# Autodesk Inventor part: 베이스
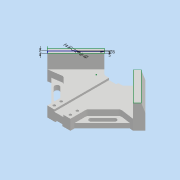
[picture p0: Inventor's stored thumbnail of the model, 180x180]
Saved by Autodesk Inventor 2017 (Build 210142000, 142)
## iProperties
Part Number: 베이스
Material: 일반
Document SubType Name: Modeling
Designer: mrc
Density: 1 g/cm^3
Appearance: 기본값
Author: mrc
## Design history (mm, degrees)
node "스케치1"
sketch "스케치2"
  geometry: L1 (0, 0)-(0, 3.931); L2 (20, -64.853)-(84.853, 0); L3 (84.853, 0)-(0, 84.853); L4 (0, 84.853)-(-84.853, 0); L5 (-84.853, 0)-(-20, -64.853); L6 (84.853, 0)-(-84.853, 0); L7 (0, -64.853)-(-20, -64.853); L8 (0, -64.853)-(20, -64.853); L9 (0, 84.853)-(35.355, 49.497); L10 (0, 84.853)-(-35.355, 49.497); L11 (24.749, 38.891)-(74.246, -10.607); L12 (-35.355, 49.497)-(-16.005, 30.147); L13 (35.355, 49.497)-(16.005, 30.147); L14 (-24.749, 38.891)-(-74.246, -10.607); L15 (0, -64.853)-(0, 30.147); L16 (0, 30.147)-(-16.005, 30.147); L17 (0, 30.147)-(16.005, 30.147); L18 (-20, -36.569)-(-49.497, -7.071); L19 (-84.853, 0)-(-63.64, -21.213); L20 (-74.246, -10.607)-(-49.497, -7.071); L21 (84.853, 0)-(63.64, -21.213); L22 (74.246, -10.607)-(49.497, -7.071); L23 (49.497, -7.071)-(20, -36.569); L24 (-20, -64.853)-(-20, -36.569); L25 (20, -64.853)-(20, -36.569); 4 further points
  constraints: 50 end point, 11 point on line, 3 perpendicular, 3 vertical, 2 horizontal, 2 midpoint, 2 parallel
  dimensions: "d10" = 120 distance of L3.end L2.end; "d13" = 20 distance of L7.start L5.end; "d14" = 20 distance of L7.start L2.start; "d15" = 50 distance of L3.end L9.end; "d16" = 50 distance of L3.end L10.end; "d17" = 15 distance between parallel lines of L3 L11; "d19" = 15 distance between parallel lines of L14 L4; "d21" = 20 distance between parallel lines of L5 L18; "d22" = 30 distance of L4.end L19.end; "d24" = 30 distance of L2.end L21.end; "d101" = 95 distance of L7.start L15.end
extrude "돌출1" new body sketch "스케치2" distance "d25" = 18; taper "d26" = 0 deg
sketch "스케치4"
  geometry: L1 (84.853, 0)-(-84.853, 0); L2 (-49.497, -7.071)-(-74.246, -10.607) reference; L3 (-24.749, 38.891)-(-16.005, 30.147) reference; L4 (-74.246, -10.607)-(-24.749, 38.891); L5 (-24.749, 38.891)-(-35.355, 49.497); L6 (24.749, 38.891)-(74.246, -10.607) reference; L7 (24.749, 38.891)-(35.355, 49.497); L8 (24.749, 38.891)-(74.246, -10.607); L9 (-35.355, 49.497)-(-84.853, 0); L10 (-84.853, 0)-(-74.246, -10.607); L11 (35.355, 49.497)-(84.853, 0); L12 (84.853, 0)-(74.246, -10.607); 2 further points
  constraints: 18 end point, 3 perpendicular, 2 midpoint
  dimensions: "d31" = 70 distance of L7.end L1.start
extrude "돌출2" join sketch "스케치4" distance "d32" = 42; taper "d33" = 0 deg
sketch "스케치5"
  geometry: L1 (0, -84.853)-(84.853, 0); L2 (84.853, 0)-(77.782, 0); L3 (-81.317, 3.536)-(-84.853, 0); L4 (84.853, 0)-(81.317, 3.536); L5 (-49.497, -7.071)-(-74.246, -10.607) reference; L6 (-68.059, -9.723)-(-49.497, -7.071); L7 (20, -36.569)-(20, -64.853) reference; L8 (20, -64.853)-(-20, -64.853) reference; L9 (-20, -64.853)-(-20, -36.569) reference; L10 (-20, -36.569)-(-49.497, -7.071) reference; L11 (-49.497, -7.071)-(-74.246, -10.607) reference; L12 (-74.246, -10.607)-(-84.853, 0) reference; L13 (-84.853, 0)-(-35.355, 49.497) reference; L14 (-35.355, 49.497)-(-16.005, 30.147) reference; L15 (-16.005, 30.147)-(16.005, 30.147) reference; L16 (16.005, 30.147)-(35.355, 49.497) reference; L17 (35.355, 49.497)-(84.853, 0) reference; L18 (84.853, 0)-(74.246, -10.607) reference; L19 (74.246, -10.607)-(49.497, -7.071) reference; L20 (49.497, -7.071)-(20, -36.569) reference; L21 (-20, -36.569)-(-49.497, -7.071) reference; L22 (-49.497, -7.071)-(-20, -36.569); L23 (-20, -64.853)-(-20, -36.569) reference; L24 (-20, -36.569)-(-20, -59.093); L25 (20, -36.569)-(20, -64.853) reference; L26 (20, -58.469)-(20, -36.569); L27 (74.246, -10.607)-(49.497, -7.071) reference; L28 (20, -36.569)-(49.497, -7.071); L29 (49.497, -7.071)-(74.246, -10.607); L30 (-84.853, 0)-(-74.246, -10.607); L31 (-20, -64.853)-(0, -84.853); L32 (0, -77.782)-(-12.929, -64.853); L33 (-20, -57.782)-(-68.059, -9.723); L34 (68.059, -9.723)-(20, -57.782); L35 (12.929, -64.853)-(0, -77.782); 2 further points
  constraints: 34 end point, 11 point on line, 4 collinear, 3 parallel, 1 perpendicular, 1 vertical alignment
extrude "돌출3" join sketch "스케치5" distance "d37" = 8; taper "d38" = 0 deg
sketch "스케치6"
  geometry: L1 (16.005, 30.147)-(-16.005, 30.147) reference; L2 (0, 30.147)-(0, -64.853); L3 (-20, -64.853)-(20, -64.853) reference; L4 (-8, 30.147)-(-8, -66.066); L5 (8, 30.147)-(8, -66.066); L6 (8, 30.147)-(-8, 30.147); L7 (-8, -66.066)-(8, -66.066); 1 further point
  constraints: 10 end point, 2 midpoint, 2 parallel, 1 collinear, 1 horizontal
  dimensions: "d39" = 8 distance between parallel lines of L2 L4; "d40" = 8 distance between parallel lines of L2 L5
extrude "돌출4" cut sketch "스케치6" distance "d41" = 3.5; taper "d42" = 0 deg
sketch "스케치7"
  geometry: L1 (20, -64.853)-(-20, -64.853) reference; L2 (0, -64.853)-(0, 30.147); L3 (-16.005, 30.147)-(16.005, 30.147) reference; L4 (6, -66.066)-(6, 30.147); L5 (-6, -66.066)-(-6, 30.147); L6 (-6, 30.147)-(6, 30.147); L7 (6, -66.066)-(-6, -66.066); 1 further point
  constraints: 10 end point, 3 parallel, 2 midpoint, 1 collinear
  dimensions: "d43" = 6 distance between parallel lines of L2 L4; "d44" = 6 distance between parallel lines of L2 L5
extrude "돌출5" cut sketch "스케치7" distance "d45" = 3; taper "d46" = 0 deg
sketch "스케치8"
  geometry: L1 (-20, -36.569)-(-20, -64.853) reference; L2 (-20, -64.853)-(-6, -64.853) reference; L3 (20, -64.853)-(20, -36.569) reference; L4 (8, -64.853)-(20, -64.853) reference; C1 r 2.25 at (14, -46.853); C2 r 2.25 at (14, -58.853); C3 r 2.25 at (-14, -46.853); C4 r 2.25 at (-14, -58.853); 1 further point
  constraints: 4 centre point
  dimensions: "d47" = 4.5 diameter of C1; "d48" = 4.5 diameter of C2; "d49" = 4.5 diameter of C3; "d50" = 4.5 diameter of C4; "d51" = 6 distance from line of L1 C4.centre; "d52" = 6 distance from line of L1 C3.centre; "d53" = 6 distance from line of L2 C4.centre; "d54" = 12 distance of C4.centre C3.centre; "d55" = 6 distance from line of L3 C1.centre; "d56" = 6 distance from line of L3 C2.centre; "d57" = 12 distance of C1.centre C2.centre; "d58" = 6 distance from line of L4 C2.centre
extrude "돌출6" cut sketch "스케치8" distance "d59" = 8; taper "d60" = 0 deg
sketch "스케치9"
  geometry: C1 r 2.25 at (14, -58.853) reference; C2 r 4 at (14, -58.853); C3 r 2.25 at (14, -46.853) reference; C4 r 4 at (14, -46.853); C5 r 2.25 at (-14, -58.853) reference; C6 r 4 at (-14, -58.853); C7 r 2.25 at (-14, -46.853) reference; C8 r 4 at (-14, -46.853); 1 further point
  constraints: 4 centre point, 4 coincident
  dimensions: "d61" = 8 diameter of C2; "d62" = 8 diameter of C4; "d63" = 8 diameter of C6; "d64" = 8 diameter of C8
extrude "돌출7" cut sketch "스케치9" distance "d65" = 10; taper "d66" = 0 deg
sketch "스케치10"
  geometry: L1 (0, 0)-(-5, 0); L2 (-15, 0)-(0, 0) reference; L3 (0, 0)-(0, 15); L4 (0, 15)-(-5, 0); 1 further point
  constraints: 6 end point, 1 point on line, 1 vertical
  dimensions: "d67" = 5 distance of L1.start L1.end; "d68" = 15 distance of L1.start L3.end
extrude "돌출8" cut sketch "스케치10" stored distance "d69" = 10; taper "d70" = 0 deg
sketch "스케치11"
  geometry: L1 (0, 0)-(0, 42) reference; L2 (0, 42)-(-5, 42); L3 (0, 42)-(-15, 42) reference; L4 (0, 42)-(0, 27); L5 (0, 27)-(-5, 42); 1 further point
  constraints: 6 end point, 2 point on line
  dimensions: "d71" = 5 distance of L1.end L2.end; "d72" = 15 distance of L1.end L4.end
extrude "돌출9" cut sketch "스케치11" stored distance "d73" = 10; taper "d74" = 0 deg
sketch "스케치14"
  geometry: L1 (-74.246, -10.607)-(-84.853, 0) reference; L2 (-74.246, -10.607)-(-77.782, -7.071); L3 (-77.782, -7.071)-(-28.339, 42.372); L4 (-24.749, 38.891)-(-31.82, 45.962) reference; L5 (31.82, 45.962)-(81.317, -3.536) reference; L6 (81.317, -3.536)-(74.246, -10.607) reference; L7 (74.246, -10.607)-(24.749, 38.891) reference; L8 (24.749, 38.891)-(31.82, 45.962) reference; L9 (-81.317, -3.536)-(-31.82, 45.962) reference; L10 (-31.82, 45.962)-(-24.749, 38.891) reference; L11 (-24.749, 38.891)-(-74.246, -10.607) reference; L12 (-74.246, -10.607)-(-81.317, -3.536) reference; 2 further points
  constraints: 4 end point, 1 perpendicular, 1 point on line, 1 other
  dimensions: "d77" = 5 distance of L1.start L2.end; "d78" = 35 distance from line of L4 point (-53.033, 17.678); "d79" = 5 distance from line of L11 point (-53.033, 17.678)
  node "절단 모서리 투영2"
sketch "스케치16"
  geometry: L1 (-74.246, -10.607)-(-84.853, 0) reference; L2 (-52.326, -21.213)-(-46.669, -15.556); L3 (-84.853, 0)-(-76.368, 8.485); L4 (-84.853, 0)-(-35.355, 49.497) reference; L5 (-52.326, -15.556)-(-26.877, -41.006); L6 (-20, -36.569)-(-20, -57.782) reference; L7 (-32.534, -41.006)-(-26.877, -35.349); L8 (-32.534, -41.006)-(-52.326, -21.213); L9 (-76.368, 2.828)-(-82.024, -2.828); L10 (-76.368, 14.142)-(-87.681, 2.828); L11 (-73.539, 11.314)-(-76.368, 14.142); L12 (-17.172, -45.054)-(-20, -42.225); L13 (-26.877, -35.349)-(-46.669, -15.556); A1 r 4 centre (-49.497, -18.385) between (-52.326, -15.556) and (-52.326, -21.213); 2 further points
  constraints: 20 end point, 6 perpendicular, 4 point on line, 2 midpoint, 2 point on circle, 1 centre point, 3 other
  dimensions: "d81" = 12 distance of L1.end L3.end; "d83" = 8 diameter of A1; "d85" = 4 distance between parallel lines of L5 L8
extrude "돌출10" cut sketch "스케치16" stored distance "d87" = 10; taper "d88" = 0 deg
sketch "스케치17"
  geometry: L1 (20, -57.782)-(20, -36.569) reference; L2 (84.853, 0)-(74.246, -10.607) reference; L3 (52.326, -15.556)-(35.355, -32.527); L4 (29.698, -38.184)-(35.355, -32.527); L5 (26.87, -35.355)-(32.527, -29.698); L6 (32.527, -41.012)-(38.184, -35.355); L7 (38.184, -35.355)-(52.326, -21.213); L8 (76.368, 2.828)-(82.024, -2.828); L9 (32.527, -29.698)-(46.669, -15.556); A1 r 4 centre (49.497, -18.385) between (52.326, -21.213) and (46.669, -15.556); A2 r 4 centre (29.698, -38.184) between (26.87, -35.355) and (32.527, -41.012); 1 further point
  constraints: 14 end point, 5 point on circle, 2 centre point, 1 coincident, 1 perpendicular
  dimensions: "d93" = 8 diameter of A1; "d94" = 8 diameter of A2; "d96" = 4 distance between parallel lines of L3 L7
extrude "돌출11" cut sketch "스케치17" stored distance "d97" = 10; taper "d98" = 0 deg
fillet "모깎기1" dims "d99" = 5
fillet "모깎기2" dims "d100" = 5
node "솔리드1"
node "절단 모서리 투영1"
other parameters: "d18" = 15, "d36" = 5, "d86" = 4, "d95" = 4
